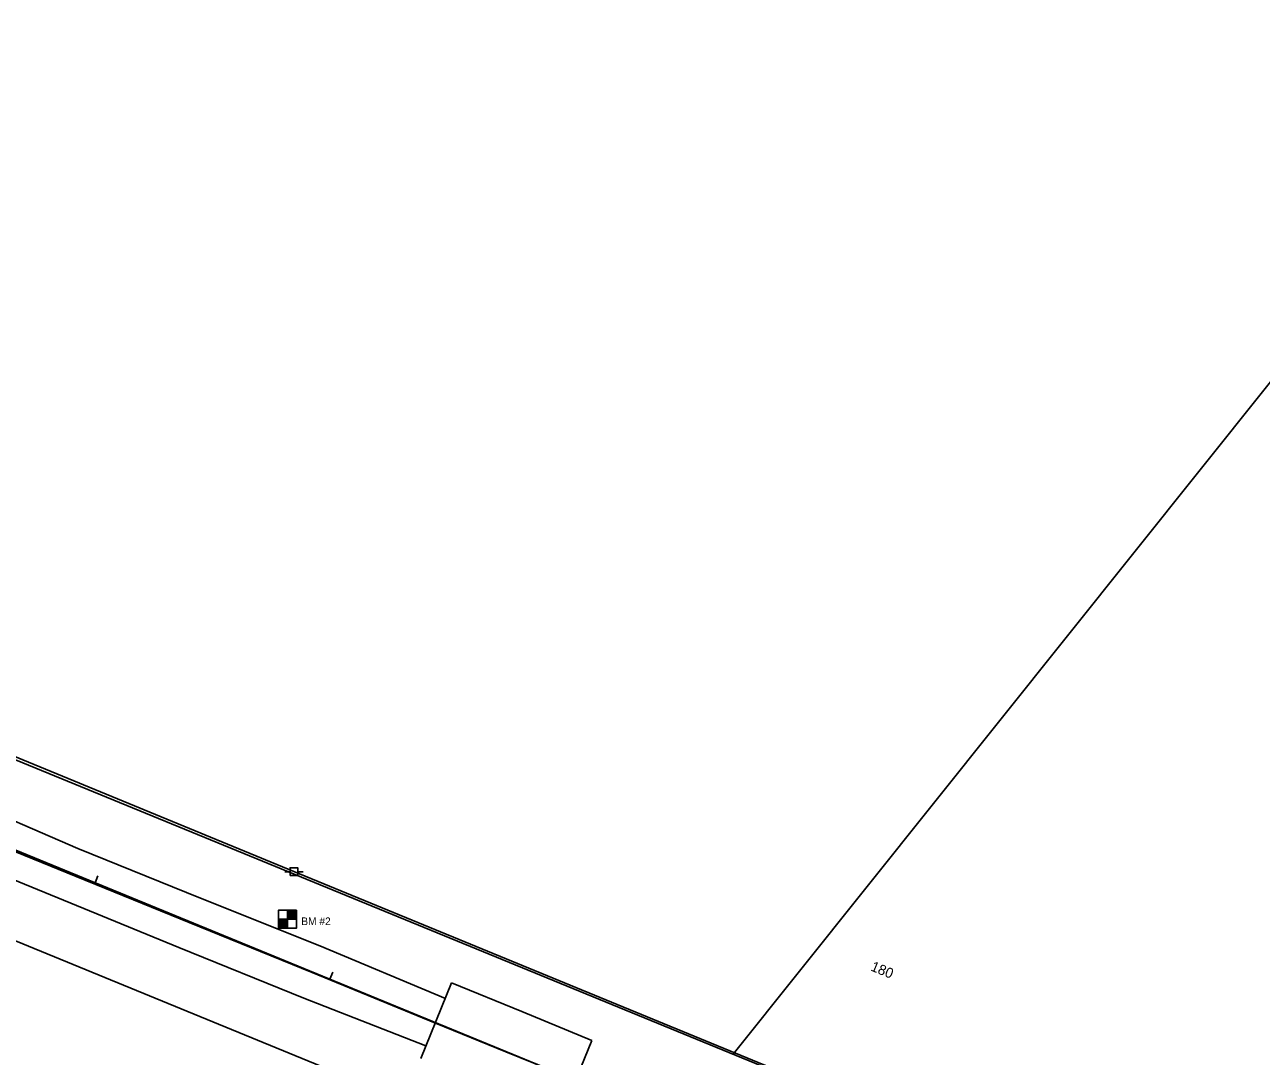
# Model space of a CAD drawing. Extents: x 1903662 to 1907233, y 1108998 to 1112872.
# Drawn here: x 1905330.5 to 1905817.9, y 1110088.7 to 1110495.2 of the extents above; entities that cross this region are included whole.
import ezdxf

# ---------------------------------------------------------------- set-up
doc = ezdxf.new("R2010")
doc.units = 0
for name, color, linetype in [('RD_DTM_BkLn1', 7, 'Continuous'), ('RD_EX_Bridge', 7, 'Continuous'), ('RD_EX_DV_Prop', 7, 'Continuous'), ('RD_EX_Road', 7, 'Continuous'), ('RD_EX_RW', 7, 'Continuous'), ('RD_EX_UT', 7, 'Continuous'), ('RD_HC_Cl', 7, 'Continuous'), ('RD_HC_Data_Tic', 7, 'Continuous'), ('RD_HC_Survey', 7, 'Continuous'), ('RD_HC_Survey_txCode', 7, 'Continuous'), ('RD_HC_TX_Sta20', 7, 'Continuous'), ('SV_Plan_Bridge', 7, 'Continuous'), ('SV_UT_Electric_Lines', 7, 'Continuous')]:
    doc.layers.add(name, color=color, linetype=linetype)

msp = doc.modelspace()

# ---------------------------------------------------------------- linework, layer by layer
at = {"layer": 'RD_DTM_BkLn1'}
msp.add_lwpolyline([(1904865.19, 1110359), (1904913.1, 1110339.8), (1904961.42, 1110320.08), (1905008.53, 1110300.58), (1905058.58, 1110280.34), (1905106.3, 1110260.53), (1905156.09, 1110239.84), (1905206.21, 1110219.59), (1905254.3, 1110199.45), (1905300.11, 1110180.14), (1905347.21, 1110160.98), (1905395.33, 1110141.42), (1905443.75, 1110121.81), (1905492.46, 1110101.83), (1905520.15, 1110090.53), (1905547.72, 1110079.36), (1905575.52, 1110068.04), (1905603.32, 1110056.68), (1905630.91, 1110045.24), (1905658.56, 1110033.72), (1905686.41, 1110022.54)], dxfattribs=at)
at = {"layer": 'RD_EX_Bridge'}
msp.add_line((1905486.65, 1110087.88), (1905498.73, 1110117.73), dxfattribs=at)
for points in [[(1905554.05, 1110094.99), (1905526.39, 1110106.44), (1905498.73, 1110117.73)], [(1905554.05, 1110094.99), (1905549.7, 1110084.36), (1905578.01, 1110072.79), (1905605.31, 1110061.65), (1905609.79, 1110072.39)]]:
    msp.add_lwpolyline(points, dxfattribs=at)
at = {"layer": 'RD_EX_DV_Prop'}
msp.add_lwpolyline([(1906353.04, 1111760.26), (1906363.74, 1111256.35), (1906298.19, 1110996.23), (1906161.99, 1110780.44), (1905609.68, 1110089.61)], dxfattribs=at)
at = {"layer": 'RD_EX_Road'}
for points in [[(1905496.35, 1110111.49), (1905446.77, 1110132.25), (1905399.76, 1110150.99), (1905351.42, 1110170.63), (1905304.67, 1110190.78), (1905258, 1110209.73), (1905210.14, 1110229.59), (1905160.61, 1110250.11), (1905111.53, 1110271.5), (1905062.64, 1110291.27), (1905013.42, 1110311.88), (1904965.6, 1110330.96), (1904917.58, 1110350.01), (1904868.56, 1110369.54)], [(1905488.55, 1110092.85), (1905440.52, 1110111.68), (1905391.25, 1110131.57), (1905343.49, 1110151.21), (1905296.63, 1110170.35), (1905249.95, 1110189.58), (1905202.45, 1110209.57), (1905152.37, 1110230.29), (1905102.47, 1110250.73), (1905054.27, 1110270.47), (1905004.76, 1110290.72), (1904957.54, 1110310), (1904909.51, 1110329.47), (1904861.73, 1110348.28)]]:
    msp.add_lwpolyline(points, dxfattribs=at)
at = {"layer": 'RD_EX_RW'}
for p, q in [((1904864.32, 1110395.12), (1906497.97, 1109725.51)), ((1904839.26, 1110334.07), (1906209.37, 1109772.47))]:
    msp.add_line(p, q, dxfattribs=at)
at = {"layer": 'RD_EX_UT'}
for p, q in [((1905433.04, 1110161.46), (1905435.1, 1110161.46)), ((1905436.6, 1110161.49), (1905436.6, 1110161.49)), ((1905438.1, 1110161.46), (1905440.24, 1110161.46))]:
    msp.add_line(p, q, dxfattribs=at)
msp.add_lwpolyline([(1904589.73, 1110482.88), (1904891.43, 1110385.65), (1905171.11, 1110270.76), (1905436.6, 1110161.49), (1905735.85, 1110038.44), (1905992.24, 1109932.67), (1906258.29, 1109823.17), (1906443.47, 1109747.31)], dxfattribs=at)
msp.add_lwpolyline([(1905435.1, 1110159.99), (1905435.1, 1110162.99), (1905438.1, 1110162.99), (1905438.1, 1110159.99)], close=True, dxfattribs=at)
at = {"layer": 'RD_HC_Cl'}
msp.add_line((1904865.19, 1110359.1), (1906221.88, 1109803.01), dxfattribs=at)
at = {"layer": 'RD_HC_Data_Tic'}
for p, q in [((1905358.21, 1110157.02), (1905359.35, 1110159.79)), ((1905450.74, 1110119.09), (1905451.88, 1110121.87))]:
    msp.add_line(p, q, dxfattribs=at)
at = {"layer": 'RD_HC_Survey'}
for p, q in [((1905434.11, 1110146.31), (1905434.11, 1110139.24)), ((1905434.15, 1110146.31), (1905434.15, 1110142.78)), ((1905434.2, 1110146.31), (1905434.2, 1110142.78)), ((1905434.25, 1110146.31), (1905434.25, 1110142.78)), ((1905434.3, 1110146.31), (1905434.3, 1110142.78)), ((1905434.35, 1110146.31), (1905434.35, 1110142.78)), ((1905434.4, 1110146.31), (1905434.4, 1110142.78)), ((1905434.45, 1110146.31), (1905434.45, 1110142.78)), ((1905434.5, 1110146.31), (1905434.5, 1110142.78)), ((1905434.55, 1110146.31), (1905434.55, 1110142.78)), ((1905434.6, 1110146.31), (1905434.6, 1110142.78)), ((1905434.65, 1110146.31), (1905434.65, 1110142.78)), ((1905434.7, 1110146.31), (1905434.7, 1110142.78)), ((1905434.75, 1110146.31), (1905434.75, 1110142.78)), ((1905434.8, 1110146.31), (1905434.8, 1110142.78)), ((1905434.85, 1110146.31), (1905434.85, 1110142.78)), ((1905434.9, 1110146.31), (1905434.9, 1110142.78)), ((1905434.95, 1110146.31), (1905434.95, 1110142.78)), ((1905435, 1110146.31), (1905435, 1110142.78)), ((1905435.05, 1110146.31), (1905435.05, 1110142.78)), ((1905435.1, 1110146.31), (1905435.1, 1110142.78)), ((1905435.15, 1110146.31), (1905435.15, 1110142.78)), ((1905435.2, 1110146.31), (1905435.2, 1110142.78)), ((1905435.25, 1110146.31), (1905435.25, 1110142.78)), ((1905435.3, 1110146.31), (1905435.3, 1110142.78)), ((1905435.35, 1110146.31), (1905435.35, 1110142.78)), ((1905435.4, 1110146.31), (1905435.4, 1110142.78)), ((1905435.45, 1110146.31), (1905435.45, 1110142.78)), ((1905435.5, 1110146.31), (1905435.5, 1110142.78)), ((1905435.55, 1110146.31), (1905435.55, 1110142.78)), ((1905435.6, 1110146.31), (1905435.6, 1110142.78)), ((1905435.65, 1110146.31), (1905435.65, 1110142.78)), ((1905435.7, 1110146.31), (1905435.7, 1110142.78)), ((1905435.75, 1110146.31), (1905435.75, 1110142.78)), ((1905435.8, 1110146.31), (1905435.8, 1110142.78)), ((1905435.85, 1110146.31), (1905435.85, 1110142.78)), ((1905435.9, 1110146.31), (1905435.9, 1110142.78)), ((1905435.95, 1110146.31), (1905435.95, 1110142.78)), ((1905436, 1110146.31), (1905436, 1110142.78)), ((1905436.05, 1110146.31), (1905436.05, 1110142.78)), ((1905436.1, 1110146.31), (1905436.1, 1110142.78)), ((1905436.15, 1110146.31), (1905436.15, 1110142.78)), ((1905436.2, 1110146.31), (1905436.2, 1110142.78)), ((1905436.25, 1110146.31), (1905436.25, 1110142.78)), ((1905436.3, 1110146.31), (1905436.3, 1110142.78)), ((1905436.35, 1110146.31), (1905436.35, 1110142.78)), ((1905436.4, 1110146.31), (1905436.4, 1110142.78)), ((1905436.45, 1110146.31), (1905436.45, 1110142.78)), ((1905436.5, 1110146.31), (1905436.5, 1110142.78)), ((1905436.55, 1110146.31), (1905436.55, 1110142.78)), ((1905436.6, 1110146.31), (1905436.6, 1110142.78)), ((1905436.65, 1110146.31), (1905436.65, 1110142.78)), ((1905436.7, 1110146.31), (1905436.7, 1110142.78)), ((1905436.75, 1110146.31), (1905436.75, 1110142.78)), ((1905436.8, 1110146.31), (1905436.8, 1110142.78)), ((1905436.85, 1110146.31), (1905436.85, 1110142.78)), ((1905436.9, 1110146.31), (1905436.9, 1110142.78)), ((1905436.95, 1110146.31), (1905436.95, 1110142.78)), ((1905437, 1110146.31), (1905437, 1110142.78)), ((1905437.05, 1110146.31), (1905437.05, 1110142.78)), ((1905437.1, 1110146.31), (1905437.1, 1110142.78)), ((1905437.15, 1110146.31), (1905437.15, 1110142.78)), ((1905437.2, 1110146.31), (1905437.2, 1110142.78)), ((1905437.25, 1110146.31), (1905437.25, 1110142.78)), ((1905437.3, 1110146.31), (1905437.3, 1110142.78)), ((1905437.35, 1110146.31), (1905437.35, 1110142.78)), ((1905437.4, 1110146.31), (1905437.4, 1110142.78)), ((1905437.45, 1110146.31), (1905437.45, 1110142.78)), ((1905437.5, 1110146.31), (1905437.5, 1110142.78)), ((1905437.55, 1110146.31), (1905437.55, 1110142.78)), ((1905437.6, 1110146.31), (1905437.6, 1110142.78)), ((1905437.65, 1110142.78), (1905430.58, 1110142.78)), ((1905430.58, 1110142.78), (1905430.58, 1110139.24)), ((1905430.63, 1110142.78), (1905430.63, 1110139.24)), ((1905430.68, 1110142.78), (1905430.68, 1110139.24)), ((1905430.73, 1110142.78), (1905430.73, 1110139.24)), ((1905430.78, 1110142.78), (1905430.78, 1110139.24)), ((1905430.83, 1110142.78), (1905430.83, 1110139.24)), ((1905430.88, 1110142.78), (1905430.88, 1110139.24)), ((1905430.93, 1110142.78), (1905430.93, 1110139.24)), ((1905430.98, 1110142.78), (1905430.98, 1110139.24)), ((1905431.03, 1110142.78), (1905431.03, 1110139.24)), ((1905431.08, 1110142.78), (1905431.08, 1110139.24)), ((1905431.13, 1110142.78), (1905431.13, 1110139.24)), ((1905431.18, 1110142.78), (1905431.18, 1110139.24)), ((1905431.23, 1110142.78), (1905431.23, 1110139.24)), ((1905431.28, 1110142.78), (1905431.28, 1110139.24)), ((1905431.33, 1110142.78), (1905431.33, 1110139.24)), ((1905431.38, 1110142.78), (1905431.38, 1110139.24)), ((1905431.43, 1110142.78), (1905431.43, 1110139.24)), ((1905431.48, 1110142.78), (1905431.48, 1110139.24)), ((1905431.53, 1110142.78), (1905431.53, 1110139.24)), ((1905431.58, 1110142.78), (1905431.58, 1110139.24)), ((1905431.63, 1110142.78), (1905431.63, 1110139.24)), ((1905431.68, 1110142.78), (1905431.68, 1110139.24)), ((1905431.73, 1110142.78), (1905431.73, 1110139.24)), ((1905431.78, 1110142.78), (1905431.78, 1110139.24)), ((1905431.83, 1110142.78), (1905431.83, 1110139.24)), ((1905431.88, 1110142.78), (1905431.88, 1110139.24)), ((1905431.93, 1110142.78), (1905431.93, 1110139.24)), ((1905431.98, 1110142.78), (1905431.98, 1110139.24)), ((1905432.03, 1110142.78), (1905432.03, 1110139.24)), ((1905432.08, 1110142.78), (1905432.08, 1110139.24)), ((1905432.13, 1110142.78), (1905432.13, 1110139.24)), ((1905432.18, 1110142.78), (1905432.18, 1110139.24)), ((1905432.23, 1110142.78), (1905432.23, 1110139.24)), ((1905432.28, 1110142.78), (1905432.28, 1110139.24)), ((1905432.33, 1110142.78), (1905432.33, 1110139.24)), ((1905432.38, 1110142.78), (1905432.38, 1110139.24)), ((1905432.43, 1110142.78), (1905432.43, 1110139.24)), ((1905432.48, 1110142.78), (1905432.48, 1110139.24)), ((1905432.53, 1110142.78), (1905432.53, 1110139.24)), ((1905432.58, 1110142.78), (1905432.58, 1110139.24)), ((1905432.63, 1110142.78), (1905432.63, 1110139.24)), ((1905432.68, 1110142.78), (1905432.68, 1110139.24)), ((1905432.73, 1110142.78), (1905432.73, 1110139.24)), ((1905432.78, 1110142.78), (1905432.78, 1110139.24)), ((1905432.83, 1110142.78), (1905432.83, 1110139.24)), ((1905432.88, 1110142.78), (1905432.88, 1110139.24)), ((1905432.93, 1110142.78), (1905432.93, 1110139.24)), ((1905432.98, 1110142.78), (1905432.98, 1110139.24)), ((1905433.03, 1110142.78), (1905433.03, 1110139.24)), ((1905433.08, 1110142.78), (1905433.08, 1110139.24)), ((1905433.13, 1110142.78), (1905433.13, 1110139.24)), ((1905433.18, 1110142.78), (1905433.18, 1110139.24)), ((1905433.23, 1110142.78), (1905433.23, 1110139.24)), ((1905433.28, 1110142.78), (1905433.28, 1110139.24)), ((1905433.33, 1110142.78), (1905433.33, 1110139.24)), ((1905433.38, 1110142.78), (1905433.38, 1110139.24)), ((1905433.43, 1110142.78), (1905433.43, 1110139.24)), ((1905433.48, 1110142.78), (1905433.48, 1110139.24)), ((1905433.53, 1110142.78), (1905433.53, 1110139.24)), ((1905433.58, 1110142.78), (1905433.58, 1110139.24)), ((1905433.63, 1110142.78), (1905433.63, 1110139.24)), ((1905433.68, 1110142.78), (1905433.68, 1110139.24)), ((1905433.73, 1110142.78), (1905433.73, 1110139.24)), ((1905433.78, 1110142.78), (1905433.78, 1110139.24)), ((1905433.83, 1110142.78), (1905433.83, 1110139.24)), ((1905433.88, 1110142.78), (1905433.88, 1110139.24)), ((1905433.93, 1110142.78), (1905433.93, 1110139.24)), ((1905433.98, 1110142.78), (1905433.98, 1110139.24)), ((1905434.03, 1110142.78), (1905434.03, 1110139.24)), ((1905434.08, 1110142.78), (1905434.08, 1110139.24))]:
    msp.add_line(p, q, dxfattribs=at)
msp.add_lwpolyline([(1905437.65, 1110146.31), (1905430.58, 1110146.31), (1905430.58, 1110139.24), (1905437.65, 1110139.24)], close=True, dxfattribs=at)
at = {"layer": 'SV_Plan_Bridge'}
msp.add_lwpolyline([(1905554.05, 1110094.99), (1905526.39, 1110106.44), (1905498.73, 1110117.73)], dxfattribs=at)
at = {"layer": 'SV_UT_Electric_Lines'}
msp.add_lwpolyline([(1904589.73, 1110482.88), (1904891.43, 1110385.65), (1905171.11, 1110270.76), (1905436.6, 1110161.49), (1905735.85, 1110038.44), (1905992.24, 1109932.67), (1906258.29, 1109823.17), (1906443.47, 1109747.31)], dxfattribs=at)

# ---------------------------------------------------------------- texts
at = {"layer": 'RD_HC_Survey_txCode'}
msp.add_text('BM #2', height=3, dxfattribs=at).set_placement((1905439.5, 1110140.43))
at = {"layer": 'RD_HC_TX_Sta20'}
msp.add_text('180', height=4, rotation=337.7118, dxfattribs=at).set_placement((1905663.61, 1110122.62))

doc.saveas('drawing.dxf')
